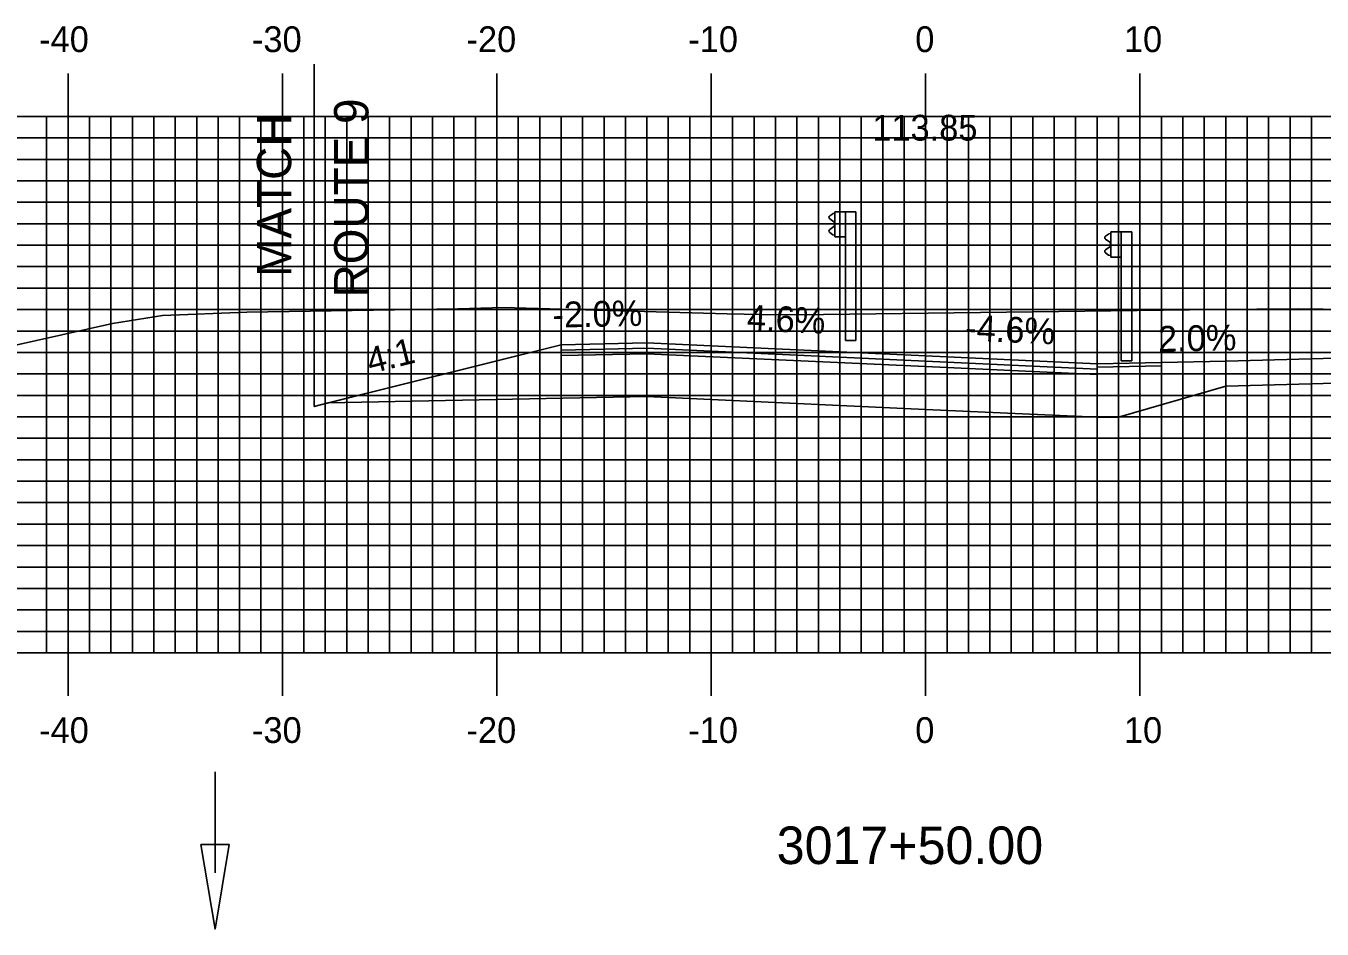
# Model space of a CAD drawing. Extents: x 1685586 to 1685929, y 461260 to 461480.
# Drawn here: x 1685709.8 to 1685770.2, y 461310.2 to 461352.3 of the extents above; entities that cross this region are included whole.
import ezdxf

# ---------------------------------------------------------------- set-up
doc = ezdxf.new("R2010")
doc.units = 0
for name, color, linetype in [('ANNOTATION', 7, 'Continuous'), ('D_Drainage_Ditch_Line', 7, 'Continuous'), ('D_Roadway_Centerline', 7, 'Continuous'), ('D_Roadway_Centerline_Text', 7, 'Continuous'), ('D_Roadway_Drive_Gravel_RT', 7, 'Continuous'), ('D_Roadway_Edge_Shoulder', 7, 'Continuous'), ('D_Roadway_Edge_TW', 7, 'Continuous'), ('D_Roadway_Pavement', 7, 'Continuous'), ('D_Roadway_SlopeLines', 7, 'Continuous'), ('D_Roadway_SubGrade', 7, 'Continuous'), ('H_V ANNOTATION', 7, 'Continuous'), ('M_Guardrail', 7, 'Continuous'), ('M_Roadway_Centerline', 7, 'Continuous'), ('MAJOR', 7, 'Continuous'), ('MINOR', 7, 'Continuous'), ('S_Roadway_Centerline', 7, 'Continuous')]:
    doc.layers.add(name, color=color, linetype=linetype)

msp = doc.modelspace()

# ---------------------------------------------------------------- linework, layer by layer
at = {"layer": 'D_Drainage_Ditch_Line'}
msp.add_line((1685718.599, 461312.823), (1685718.599, 461317.522), dxfattribs=at)
msp.add_lwpolyline([(1685719.255, 461314.135), (1685717.943, 461314.135), (1685718.599, 461310.198)], close=True, dxfattribs=at)
at = {"layer": 'D_Roadway_Centerline'}
msp.add_lwpolyline([(1685723.221, 461334.555), (1685723.873, 461334.718), (1685734.742, 461337.435), (1685738.742, 461337.515), (1685751.742, 461336.917), (1685759.742, 461336.549)], dxfattribs=at)
at = {"layer": 'D_Roadway_Drive_Gravel_RT'}
for p, q in [((1685762.742, 461336.609), (1685762.742, 461336.443)), ((1685760.742, 461334.049), (1685765.742, 461335.503)), ((1685759.742, 461334.049), (1685760.742, 461334.049))]:
    msp.add_line(p, q, dxfattribs=at)
for points in [[(1685759.742, 461336.549), (1685765.742, 461336.669), (1685858.314, 461339.198)], [(1685765.742, 461335.502), (1685858.314, 461338.031)], [(1685759.746, 461336.383), (1685762.742, 461336.443)]]:
    msp.add_lwpolyline(points, dxfattribs=at)
at = {"layer": 'D_Roadway_Edge_Shoulder'}
for points in [[(1685738.742, 461337.515), (1685734.742, 461337.435), (1685734.742, 461337.185), (1685738.742, 461337.265)], [(1685738.742, 461337.265), (1685734.742, 461337.185), (1685734.742, 461336.935), (1685738.742, 461337.015)], [(1685751.742, 461336.667), (1685759.742, 461336.299), (1685759.742, 461336.049), (1685751.742, 461336.417)]]:
    msp.add_lwpolyline(points, close=True, dxfattribs=at)
msp.add_lwpolyline([(1685759.742, 461336.549), (1685759.742, 461336.299), (1685751.742, 461336.667), (1685751.742, 461336.917), (1685759.742, 461336.549)], dxfattribs=at)
at = {"layer": 'D_Roadway_Edge_TW'}
msp.add_lwpolyline([(1685738.742, 461337.515), (1685751.742, 461336.917), (1685751.742, 461336.667), (1685738.742, 461337.265)], close=True, dxfattribs=at)
at = {"layer": 'D_Roadway_Pavement'}
msp.add_lwpolyline([(1685738.742, 461337.265), (1685751.742, 461336.667), (1685751.742, 461336.417), (1685738.742, 461337.015)], close=True, dxfattribs=at)
for points in [[(1685738.742, 461337.265), (1685738.742, 461337.015)], [(1685738.742, 461337.265), (1685738.742, 461337.015)], [(1685751.742, 461336.667), (1685751.742, 461336.417)], [(1685751.742, 461336.667), (1685751.742, 461336.417)], [(1685751.742, 461336.667), (1685751.742, 461336.417)]]:
    msp.add_lwpolyline(points, dxfattribs=at)
at = {"layer": 'D_Roadway_SlopeLines'}
msp.add_lwpolyline([(1685734.742, 461337.435), (1685723.221, 461334.555)], dxfattribs=at)
at = {"layer": 'D_Roadway_SubGrade'}
msp.add_line((1685723.221, 461350.507), (1685723.221, 461334.555), dxfattribs=at)
for points in [[(1685738.742, 461335.015), (1685723.873, 461334.718), (1685734.742, 461337.435), (1685734.742, 461337.185), (1685738.742, 461337.265), (1685738.742, 461337.015)], [(1685738.742, 461337.015), (1685751.742, 461336.417), (1685751.742, 461334.417), (1685738.742, 461335.015)], [(1685751.742, 461336.417), (1685751.742, 461336.667), (1685759.742, 461336.299), (1685759.742, 461336.549), (1685759.742, 461334.049), (1685751.742, 461334.417)]]:
    msp.add_lwpolyline(points, close=True, dxfattribs=at)
at = {"layer": 'M_Guardrail'}
for p, q in [((1685747.513, 461343.632), (1685748.003, 461343.632)), ((1685747.513, 461342.465), (1685747.513, 461343.632)), ((1685748.003, 461343.632), (1685748.494, 461343.632)), ((1685748.003, 461343.632), (1685748.003, 461342.465)), ((1685748.494, 461343.632), (1685748.494, 461337.632)), ((1685747.415, 461343.538), (1685747.271, 461343.438)), ((1685747.271, 461343.295), (1685747.466, 461343.158)), ((1685747.513, 461343.559), (1685747.431, 461343.545)), ((1685747.5, 461343.094), (1685747.5, 461343.003)), ((1685747.466, 461342.939), (1685747.271, 461342.803)), ((1685747.271, 461342.659), (1685747.415, 461342.559)), ((1685747.431, 461342.553), (1685747.513, 461342.538)), ((1685748.003, 461342.465), (1685747.513, 461342.465)), ((1685748.003, 461337.632), (1685748.003, 461342.465)), ((1685760.279, 461342.592), (1685760.136, 461342.492)), ((1685760.378, 461342.614), (1685760.296, 461342.599)), ((1685760.378, 461342.687), (1685760.868, 461342.687)), ((1685760.378, 461341.52), (1685760.378, 461342.687)), ((1685760.868, 461342.687), (1685761.359, 461342.687)), ((1685760.868, 461342.687), (1685760.868, 461341.52)), ((1685761.359, 461342.687), (1685761.359, 461336.687)), ((1685760.136, 461342.349), (1685760.331, 461342.213)), ((1685760.331, 461341.993), (1685760.136, 461341.857)), ((1685760.365, 461342.149), (1685760.365, 461342.058)), ((1685760.136, 461341.714), (1685760.279, 461341.614)), ((1685760.296, 461341.607), (1685760.378, 461341.593)), ((1685760.868, 461341.52), (1685760.378, 461341.52)), ((1685760.868, 461336.687), (1685760.868, 461341.52)), ((1685748.003, 461337.632), (1685748.494, 461337.632)), ((1685760.868, 461336.687), (1685761.359, 461336.687))]:
    msp.add_line(p, q, dxfattribs=at)
for centre, major_axis, start_param, end_param in [((1685747.321, 461343.366), (-0.0877, 0), 5.323254, 7.243116), ((1685747.438, 461343.504), (-0.0417, 0), 4.886922, 5.323254), ((1685747.421, 461343.094), (0.0789, 0), 0, 0.959931), ((1685747.421, 461343.003), (0.0789, 0), 5.323254, 6.283185), ((1685747.321, 461342.731), (-0.0877, 0), 5.323254, 7.243116), ((1685747.438, 461342.593), (-0.0417, 0), 0.959931, 1.396263), ((1685760.186, 461342.421), (-0.0877, 0), 5.323254, 7.243116), ((1685760.303, 461342.558), (-0.0417, 0), 4.886922, 5.323254), ((1685760.186, 461341.786), (-0.0877, 0), 5.323254, 7.243116), ((1685760.286, 461342.149), (0.0789, 0), 0, 0.959931), ((1685760.286, 461342.058), (0.0789, 0), 5.323254, 6.283185), ((1685760.303, 461341.648), (-0.0417, 0), 0.959931, 1.396263)]:
    msp.add_ellipse(centre, major_axis=major_axis, ratio=0.995501, start_param=start_param, end_param=end_param, dxfattribs=at)
at = {"layer": 'MAJOR'}
for p, q in [((1685711.742, 461350.076), (1685711.742, 461348.072)), ((1685721.742, 461350.076), (1685721.742, 461348.072)), ((1685731.742, 461350.076), (1685731.742, 461348.072)), ((1685741.742, 461350.076), (1685741.742, 461348.072)), ((1685751.742, 461350.076), (1685751.742, 461348.072)), ((1685761.742, 461350.076), (1685761.742, 461348.072)), ((1685611.742, 461348.072), (1685891.742, 461348.072)), ((1685611.742, 461348.072), (1685891.742, 461348.072)), ((1685711.742, 461323.072), (1685711.742, 461348.072)), ((1685721.742, 461323.072), (1685721.742, 461348.072)), ((1685731.742, 461323.072), (1685731.742, 461348.072)), ((1685741.742, 461323.072), (1685741.742, 461348.072)), ((1685751.742, 461323.072), (1685751.742, 461348.072)), ((1685761.742, 461323.072), (1685761.742, 461348.072)), ((1685611.742, 461343.072), (1685891.742, 461343.072)), ((1685611.742, 461338.072), (1685891.742, 461338.072)), ((1685611.742, 461333.072), (1685891.742, 461333.072)), ((1685611.742, 461328.072), (1685891.742, 461328.072)), ((1685611.742, 461323.072), (1685891.742, 461323.072)), ((1685611.742, 461323.072), (1685891.742, 461323.072)), ((1685711.742, 461321.068), (1685711.742, 461323.072)), ((1685721.742, 461321.068), (1685721.742, 461323.072)), ((1685731.742, 461321.068), (1685731.742, 461323.072)), ((1685741.742, 461321.068), (1685741.742, 461323.072)), ((1685751.742, 461321.068), (1685751.742, 461323.072)), ((1685761.742, 461321.068), (1685761.742, 461323.072))]:
    msp.add_line(p, q, dxfattribs=at)
at = {"layer": 'MINOR'}
for p, q in [((1685710.742, 461323.072), (1685710.742, 461348.072)), ((1685712.742, 461323.072), (1685712.742, 461348.072)), ((1685713.742, 461323.072), (1685713.742, 461348.072)), ((1685714.742, 461323.072), (1685714.742, 461348.072)), ((1685715.742, 461323.072), (1685715.742, 461348.072)), ((1685716.742, 461323.072), (1685716.742, 461348.072)), ((1685717.742, 461323.072), (1685717.742, 461348.072)), ((1685718.742, 461323.072), (1685718.742, 461348.072)), ((1685719.742, 461323.072), (1685719.742, 461348.072)), ((1685720.742, 461323.072), (1685720.742, 461348.072)), ((1685722.742, 461323.072), (1685722.742, 461348.072)), ((1685723.742, 461323.072), (1685723.742, 461348.072)), ((1685724.742, 461323.072), (1685724.742, 461348.072)), ((1685725.742, 461323.072), (1685725.742, 461348.072)), ((1685726.742, 461323.072), (1685726.742, 461348.072)), ((1685727.742, 461323.072), (1685727.742, 461348.072)), ((1685728.742, 461323.072), (1685728.742, 461348.072)), ((1685729.742, 461323.072), (1685729.742, 461348.072)), ((1685730.742, 461323.072), (1685730.742, 461348.072)), ((1685732.742, 461323.072), (1685732.742, 461348.072)), ((1685733.742, 461323.072), (1685733.742, 461348.072)), ((1685734.742, 461323.072), (1685734.742, 461348.072)), ((1685735.742, 461323.072), (1685735.742, 461348.072)), ((1685736.742, 461323.072), (1685736.742, 461348.072)), ((1685737.742, 461323.072), (1685737.742, 461348.072)), ((1685738.742, 461323.072), (1685738.742, 461348.072)), ((1685739.742, 461323.072), (1685739.742, 461348.072)), ((1685740.742, 461323.072), (1685740.742, 461348.072)), ((1685742.742, 461323.072), (1685742.742, 461348.072)), ((1685743.742, 461323.072), (1685743.742, 461348.072)), ((1685744.742, 461323.072), (1685744.742, 461348.072)), ((1685745.742, 461323.072), (1685745.742, 461348.072)), ((1685746.742, 461323.072), (1685746.742, 461348.072)), ((1685747.742, 461323.072), (1685747.742, 461348.072)), ((1685748.742, 461323.072), (1685748.742, 461348.072)), ((1685749.742, 461323.072), (1685749.742, 461348.072)), ((1685750.742, 461323.072), (1685750.742, 461348.072)), ((1685752.742, 461323.072), (1685752.742, 461348.072)), ((1685753.742, 461323.072), (1685753.742, 461348.072)), ((1685754.742, 461323.072), (1685754.742, 461348.072)), ((1685755.742, 461323.072), (1685755.742, 461348.072)), ((1685756.742, 461323.072), (1685756.742, 461348.072)), ((1685757.742, 461323.072), (1685757.742, 461348.072)), ((1685758.742, 461323.072), (1685758.742, 461348.072)), ((1685759.742, 461323.072), (1685759.742, 461348.072)), ((1685760.742, 461323.072), (1685760.742, 461348.072)), ((1685762.742, 461323.072), (1685762.742, 461348.072)), ((1685763.742, 461323.072), (1685763.742, 461348.072)), ((1685764.742, 461323.072), (1685764.742, 461348.072)), ((1685765.742, 461323.072), (1685765.742, 461348.072)), ((1685766.742, 461323.072), (1685766.742, 461348.072)), ((1685767.742, 461323.072), (1685767.742, 461348.072)), ((1685768.742, 461323.072), (1685768.742, 461348.072)), ((1685769.742, 461323.072), (1685769.742, 461348.072)), ((1685611.742, 461347.072), (1685891.742, 461347.072)), ((1685611.742, 461346.072), (1685891.742, 461346.072)), ((1685611.742, 461345.072), (1685891.742, 461345.072)), ((1685611.742, 461344.072), (1685891.742, 461344.072)), ((1685611.742, 461342.072), (1685891.742, 461342.072)), ((1685611.742, 461341.072), (1685891.742, 461341.072)), ((1685611.742, 461340.072), (1685891.742, 461340.072)), ((1685611.742, 461339.072), (1685891.742, 461339.072)), ((1685611.742, 461337.072), (1685891.742, 461337.072)), ((1685611.742, 461336.072), (1685891.742, 461336.072)), ((1685611.742, 461335.072), (1685891.742, 461335.072)), ((1685611.742, 461334.072), (1685891.742, 461334.072)), ((1685611.742, 461332.072), (1685891.742, 461332.072)), ((1685611.742, 461331.072), (1685891.742, 461331.072)), ((1685611.742, 461330.072), (1685891.742, 461330.072)), ((1685611.742, 461329.072), (1685891.742, 461329.072)), ((1685611.742, 461327.072), (1685891.742, 461327.072)), ((1685611.742, 461326.072), (1685891.742, 461326.072)), ((1685611.742, 461325.072), (1685891.742, 461325.072)), ((1685611.742, 461324.072), (1685891.742, 461324.072))]:
    msp.add_line(p, q, dxfattribs=at)
at = {"layer": 'S_Roadway_Centerline'}
msp.add_lwpolyline([(1685697.536, 461334.78), (1685713.82, 461338.419), (1685716.154, 461338.791), (1685720.089, 461338.944), (1685729.931, 461339.099), (1685731.536, 461339.157), (1685732.443, 461339.164), (1685732.56, 461339.148), (1685742.492, 461338.866), (1685744.08, 461338.835), (1685745.766, 461338.818), (1685765.26, 461339.067), (1685769.129, 461339.103), (1685776.116, 461339.015)], dxfattribs=at)

# ---------------------------------------------------------------- texts
at = {"layer": 'ANNOTATION'}
for s, height, rotation, p in [('ROUTE 9', 1.6, 90, (1685725.752, 461339.636)), ('MATCH', 1.6, 90, (1685722.152, 461340.598)), ('-2.0%', 1.2, 1.14576, (1685734.349, 461338.228)), ('4.6%', 1.2, 357.36625, (1685743.389, 461338.104)), ('-4.6%', 1.2, 357.36625, (1685753.568, 461337.636)), ('2.0%', 1.2, 1.14576, (1685762.594, 461337.102)), ('4:1', 1.2, 14.03624, (1685725.843, 461336.072))]:
    msp.add_text(s, height=height, rotation=rotation, dxfattribs=at).set_placement(p)
at = {"layer": 'D_Roadway_Centerline_Text'}
msp.add_text('113.85', height=1.2, dxfattribs=at).set_placement((1685749.255, 461346.947))
at = {"layer": 'H_V ANNOTATION'}
for s, height, p in [('-40', 1.2, (1685710.394, 461351.072)), ('-30', 1.2, (1685720.319, 461351.072)), ('-20', 1.2, (1685730.329, 461351.072)), ('-10', 1.2, (1685740.672, 461351.072)), ('0', 1.2, (1685751.261, 461351.072)), ('10', 1.2, (1685760.993, 461351.072)), ('-40', 1.2, (1685710.394, 461318.872)), ('-30', 1.2, (1685720.319, 461318.872)), ('-20', 1.2, (1685730.329, 461318.872)), ('-10', 1.2, (1685740.672, 461318.872)), ('0', 1.2, (1685751.261, 461318.872)), ('10', 1.2, (1685760.993, 461318.872)), ('3017+50.00', 1.75, (1685744.798, 461313.228))]:
    msp.add_text(s, height=height, dxfattribs=at).set_placement(p)
at = {"layer": 'M_Roadway_Centerline'}
for s, p in [('C', (1685732.437, 461339.164)), ('L', (1685732.443, 461339.157))]:
    msp.add_text(s, height=0.0146, dxfattribs=at).set_placement(p)

doc.saveas('drawing.dxf')
